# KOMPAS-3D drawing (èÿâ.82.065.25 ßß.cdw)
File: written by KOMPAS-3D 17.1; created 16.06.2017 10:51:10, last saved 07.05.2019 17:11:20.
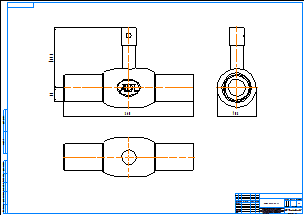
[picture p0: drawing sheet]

Sheet 1: A1, landscape

Title block, sheet 1: name: КШГ.82.065.25 сс; material: Внимание! Данный продукт является объектом авторского права ООО «Торговый Дом АДЛ». / Запрещается изменение, копирование, распространение / (в том числе путем копирования на другие сайты и ресурсы в Интернете) / или любое иное использование информации и объектов без предварительного / согласия правообладателя (ООО «Торговый Дом АДЛ»).; scale: 1:1; sheets: 1; organisation: ООО "Торговый дом АДЛ"; sheet format: A1; stored path: C:\Users\tra\Desktop\2д чертежи\Шаровые краны БИВАЛ\КШ_Бивал_серия_82_85\KOMPAS 2D\КШГ.82.065.25 сс.cdw

Views: Спереди 1, Проекционный вид 2, Проекционный вид 3
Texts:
  Klimkovich
  ADL
Dimensions and other numbers on the sheet: 360; 167,3; 38; 108; 1:1; 1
